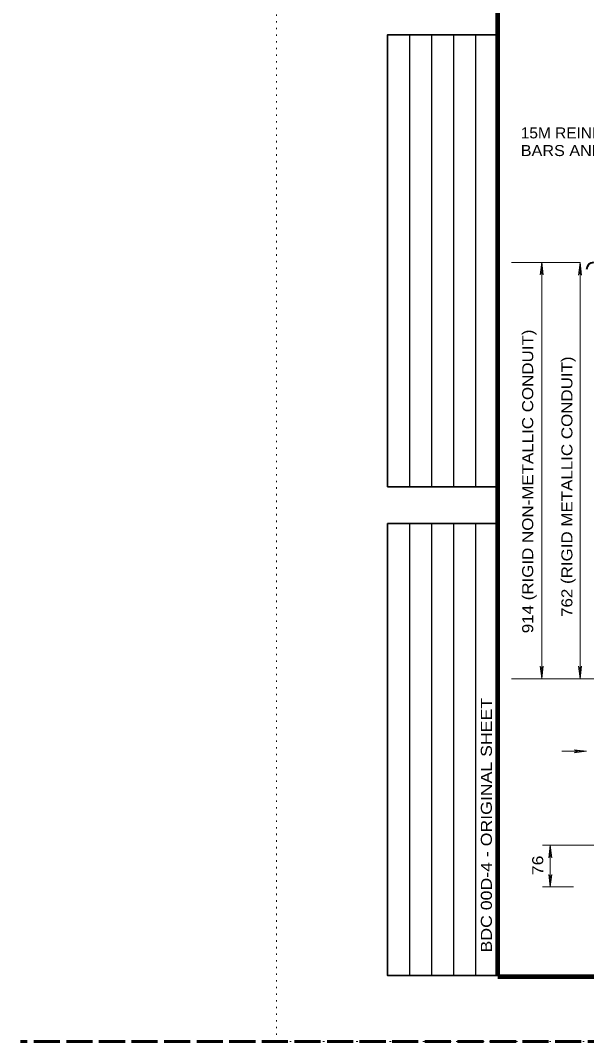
# Model space of a CAD drawing. Extents: x 312583 to 312854, y 144419 to 144597.
# Drawn here: x 312583.5 to 312622.6, y 144418.6 to 144489.1 of the extents above; entities that cross this region are included whole.
import ezdxf

# ---------------------------------------------------------------- set-up
doc = ezdxf.new("R2010")
doc.units = 0
doc.header["$LTSCALE"] = 0.3
doc.linetypes.add('DOTTED', pattern=[1.5, 0.3, -1.2])
doc.linetypes.add('LONG_DASHED', pattern=[7.5, 6, -1.5])
doc.layers.add('1', color=7, linetype='Continuous', lineweight=13)
doc.layers.add('63', color=7, linetype='DOTTED', lineweight=13)

msp = doc.modelspace()

# ---------------------------------------------------------------- linework, layer by layer
at = {"layer": '1', "lineweight": 158}
for p, q in [((312616.5, 144423.1446), (312616.5, 144582.2946)), ((312616.5, 144423.0846), (312849, 144423.0846))]:
    msp.add_line(p, q, dxfattribs=at)
at = {"layer": '1', "lineweight": 25}
for p, q in [((312610.4087, 144456.901), (312610.4087, 144488.1192)), ((312611.9315, 144456.901), (312611.9315, 144488.1192)), ((312613.4543, 144456.901), (312613.4543, 144488.1192)), ((312614.9772, 144456.901), (312614.9772, 144488.1192)), ((312610.4087, 144423.1446), (312610.4087, 144454.3629)), ((312611.9315, 144423.1446), (312611.9315, 144454.3629)), ((312613.4543, 144423.1446), (312613.4543, 144454.3629)), ((312614.9772, 144423.1446), (312614.9772, 144454.3629))]:
    msp.add_line(p, q, dxfattribs=at)
at = {"layer": '1'}
for p, q in [((312622.17, 144472.3914), (312617.434, 144472.3914)), ((312619.527, 144472.4072), (312619.4196, 144471.5409)), ((312619.527, 144443.6572), (312619.527, 144472.4072)), ((312619.527, 144472.4072), (312619.6343, 144471.5409)), ((312622.17, 144472.3914), (312622.0627, 144471.5251)), ((312622.17, 144443.6414), (312622.17, 144472.3914)), ((312622.17, 144472.3914), (312622.2773, 144471.5251)), ((312619.4196, 144471.5409), (312619.527, 144471.8169)), ((312619.6343, 144471.5409), (312619.527, 144471.8169)), ((312622.0627, 144471.5251), (312622.17, 144471.8011)), ((312622.2773, 144471.5251), (312622.17, 144471.8011)), ((312619.4196, 144444.5236), (312619.527, 144444.2476)), ((312619.527, 144443.6572), (312619.4196, 144444.5236)), ((312619.6343, 144444.5236), (312619.527, 144444.2476)), ((312619.527, 144443.6572), (312619.6343, 144444.5236)), ((312622.0627, 144444.5078), (312622.17, 144444.2318)), ((312622.17, 144443.6414), (312622.0627, 144444.5078)), ((312622.2773, 144444.5078), (312622.17, 144444.2318)), ((312622.17, 144443.6414), (312622.2773, 144444.5078)), ((312623.987, 144443.6414), (312617.434, 144443.6414)), ((312620.9197, 144438.6357), (312622.6217, 144438.6357)), ((312621.7553, 144438.743), (312622.0313, 144438.6357)), ((312622.6217, 144438.6357), (312621.7553, 144438.743)), ((312621.7553, 144438.5283), (312622.0313, 144438.6357)), ((312622.6217, 144438.6357), (312621.7553, 144438.5283)), ((312623.8567, 144432.1414), (312619.5864, 144432.1414)), ((312620.1154, 144432.1414), (312620.008, 144431.2751)), ((312620.1154, 144429.2664), (312620.1154, 144432.1414)), ((312620.1154, 144432.1414), (312620.2227, 144431.2751)), ((312620.008, 144431.2751), (312620.1154, 144431.5511)), ((312620.2227, 144431.2751), (312620.1154, 144431.5511)), ((312620.008, 144430.1328), (312620.1154, 144429.8568)), ((312620.1154, 144429.2664), (312620.008, 144430.1328)), ((312620.2227, 144430.1328), (312620.1154, 144429.8568)), ((312620.1154, 144429.2664), (312620.2227, 144430.1328)), ((312621.7177, 144429.2664), (312619.5864, 144429.2664))]:
    msp.add_line(p, q, dxfattribs=at)
at = {"layer": '1', "linetype": 'LONG_DASHED', "lineweight": 60}
msp.add_line((312851.75, 144418.5846), (312583.526, 144418.5846), dxfattribs=at)
at = {"layer": '1', "lineweight": 35}
for points in [[(312616.5, 144456.901), (312608.8858, 144456.901), (312608.8858, 144488.1192), (312616.5, 144488.1192)], [(312616.5, 144423.1446), (312608.8858, 144423.1446), (312608.8858, 144454.3629), (312616.5, 144454.3629)]]:
    msp.add_lwpolyline(points, dxfattribs=at)
at = {"layer": '1', "lineweight": 40}
msp.add_arc((312623.0977, 144471.9132), 0.4792, 90, 180, dxfattribs=at)
at = {"layer": '63'}
msp.add_line((312601.2, 144418.5846), (312601.2, 144596.7846), dxfattribs=at)
msp.add_lwpolyline([(312601.2, 144418.5846), (312853.5, 144418.5846), (312853.5, 144596.7846)], dxfattribs=at)

# ---------------------------------------------------------------- texts
at = {"layer": '1'}
for s, width, p in [('15M REINFORCING', 1.05, (312618.0771, 144480.9652)), ('BARS AND HOOPS', 1.1, (312618.0771, 144479.7452))]:
    msp.add_text(s, height=0.76, dxfattribs=dict(at, width=width)).set_placement(p)
for s, height, width, p in [('914 (RIGID NON-METALLIC CONDUIT)', 0.76, 1.15, (312618.9358, 144446.7865)), ('762 (RIGID METALLIC CONDUIT)', 0.76, 1.15, (312621.6424, 144447.9156)), ('BDC 00D-4 - ORIGINAL SHEET', 0.7614, 1.2, (312616.0832, 144424.7374)), ('76 ', 0.76, 1.2, (312619.6264, 144430.0756))]:
    msp.add_text(s, height=height, rotation=90, dxfattribs=dict(at, width=width)).set_placement(p)

doc.saveas('drawing.dxf')
